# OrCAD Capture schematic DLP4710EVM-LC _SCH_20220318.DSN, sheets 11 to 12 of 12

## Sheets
11 P06: DLPC3479_GPIO,LED_SEL,TRIG: size D
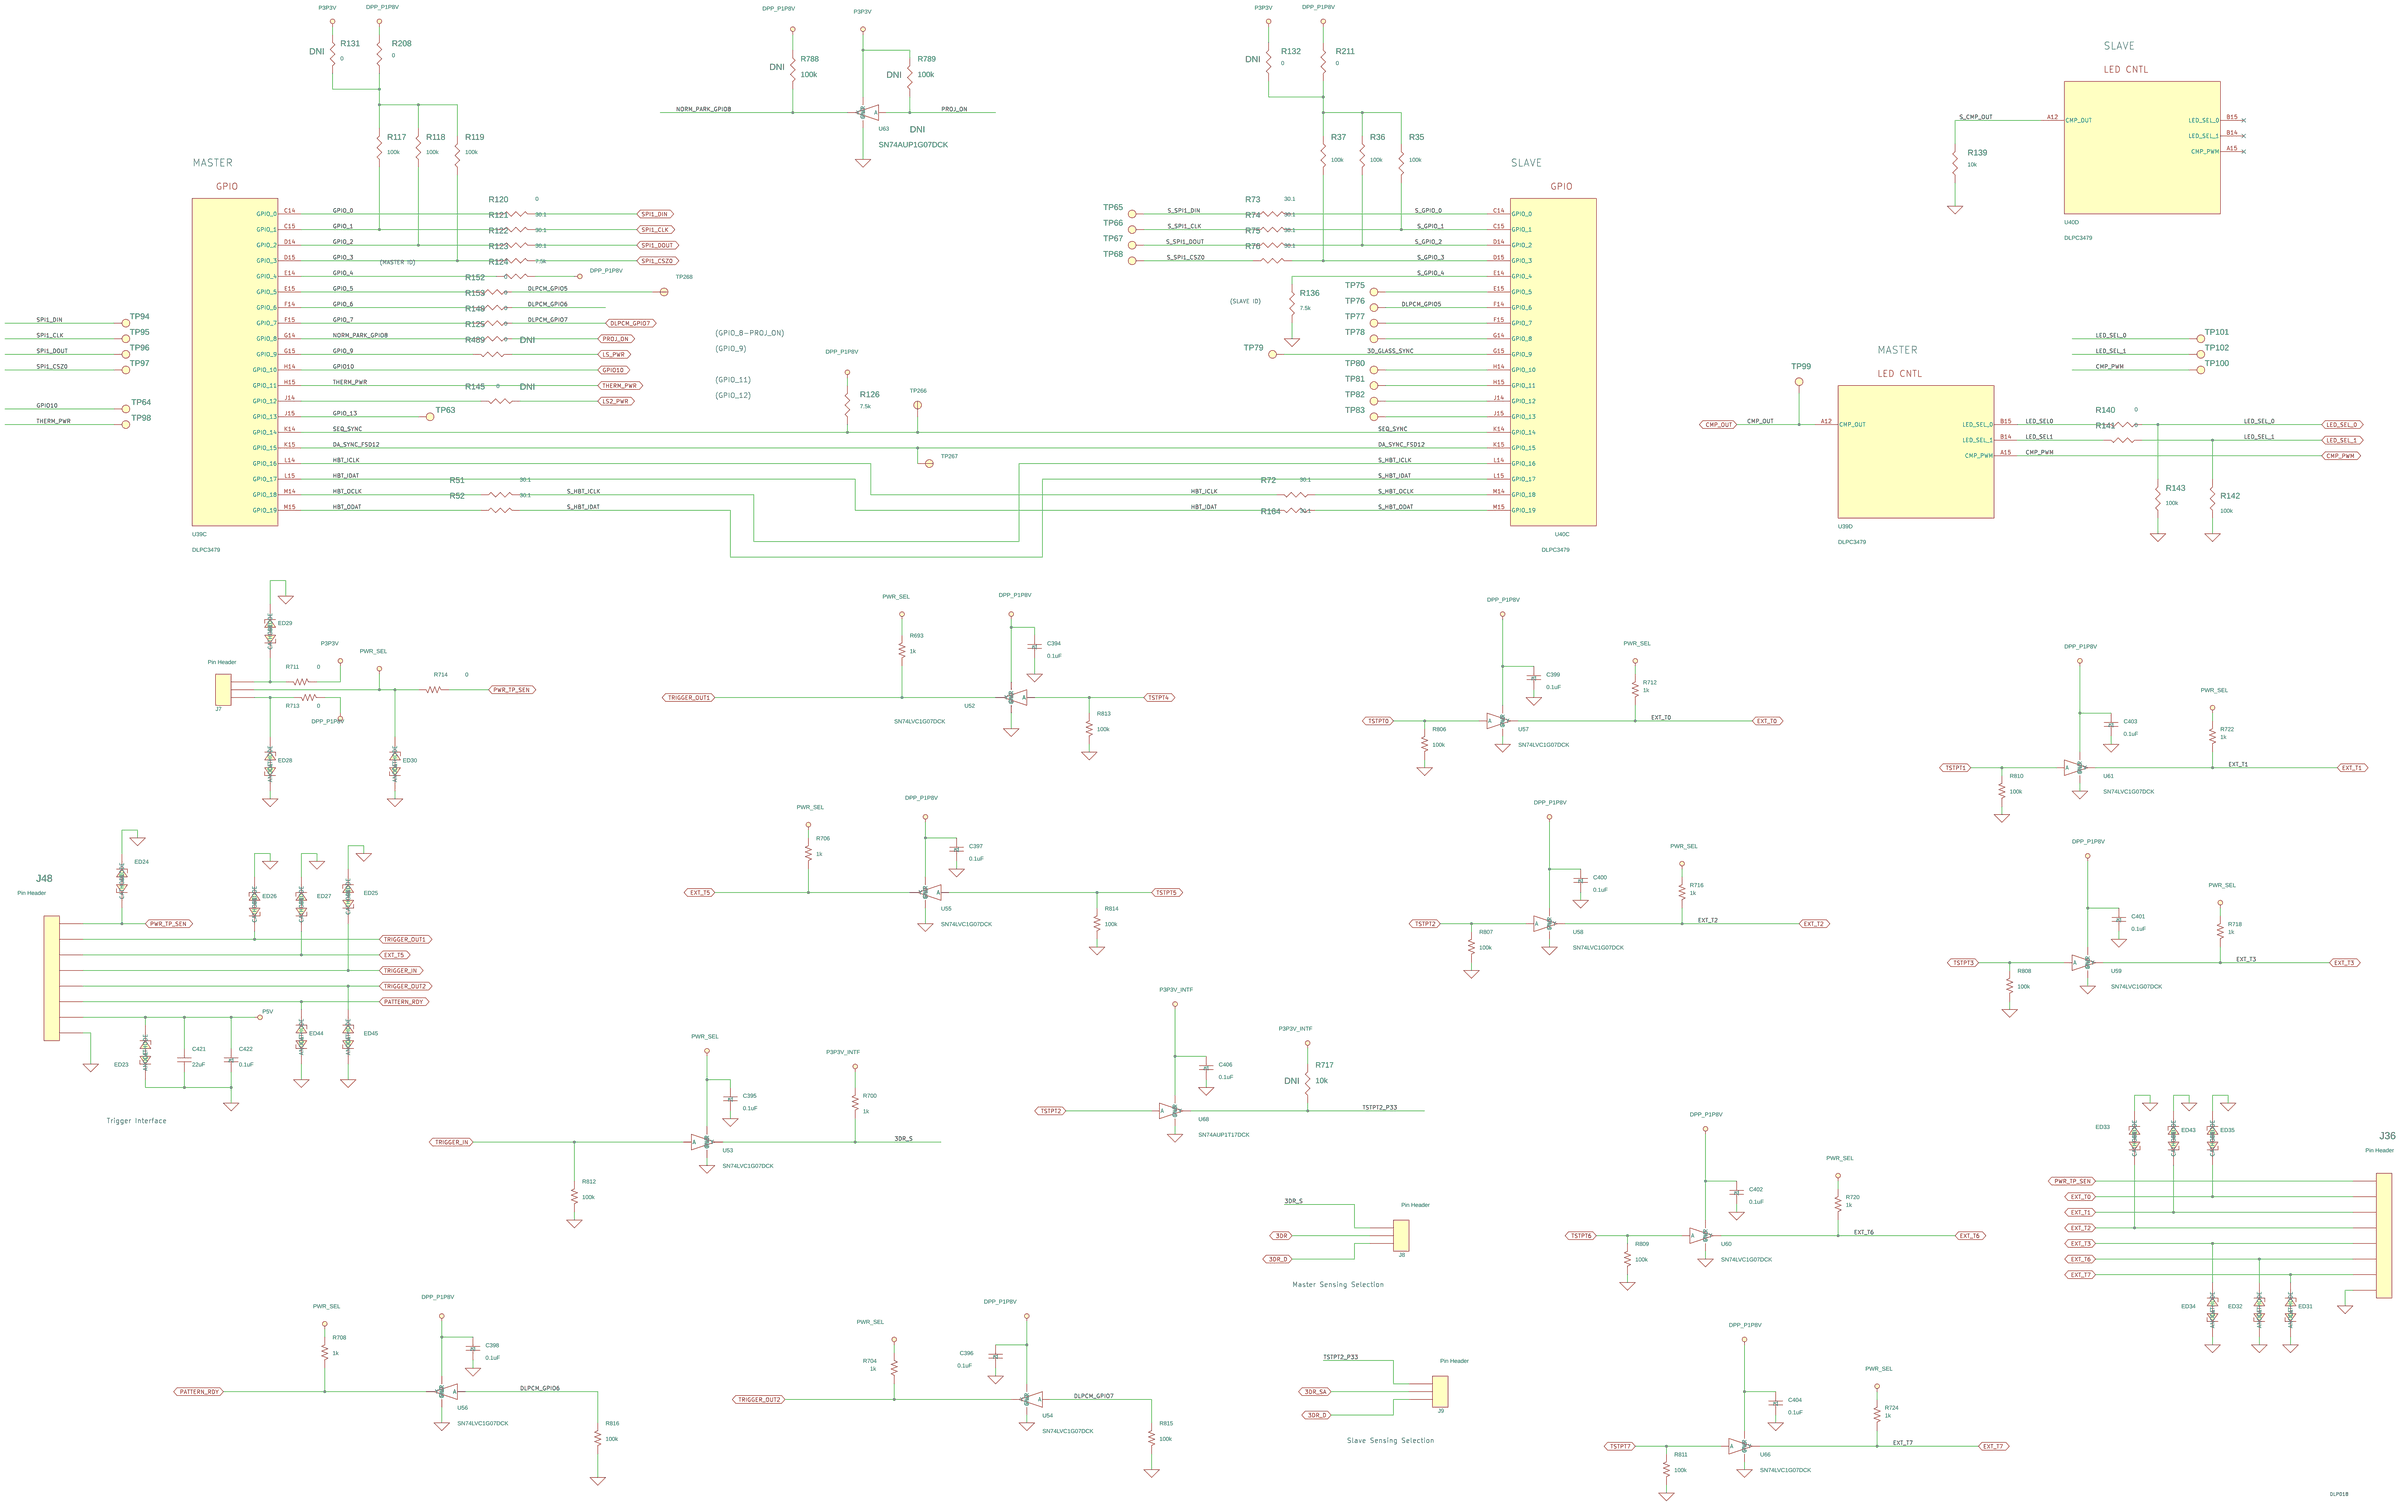
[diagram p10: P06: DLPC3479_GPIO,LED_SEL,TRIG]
12 P10: DLPA3005_PMIC & LED Driver: size D
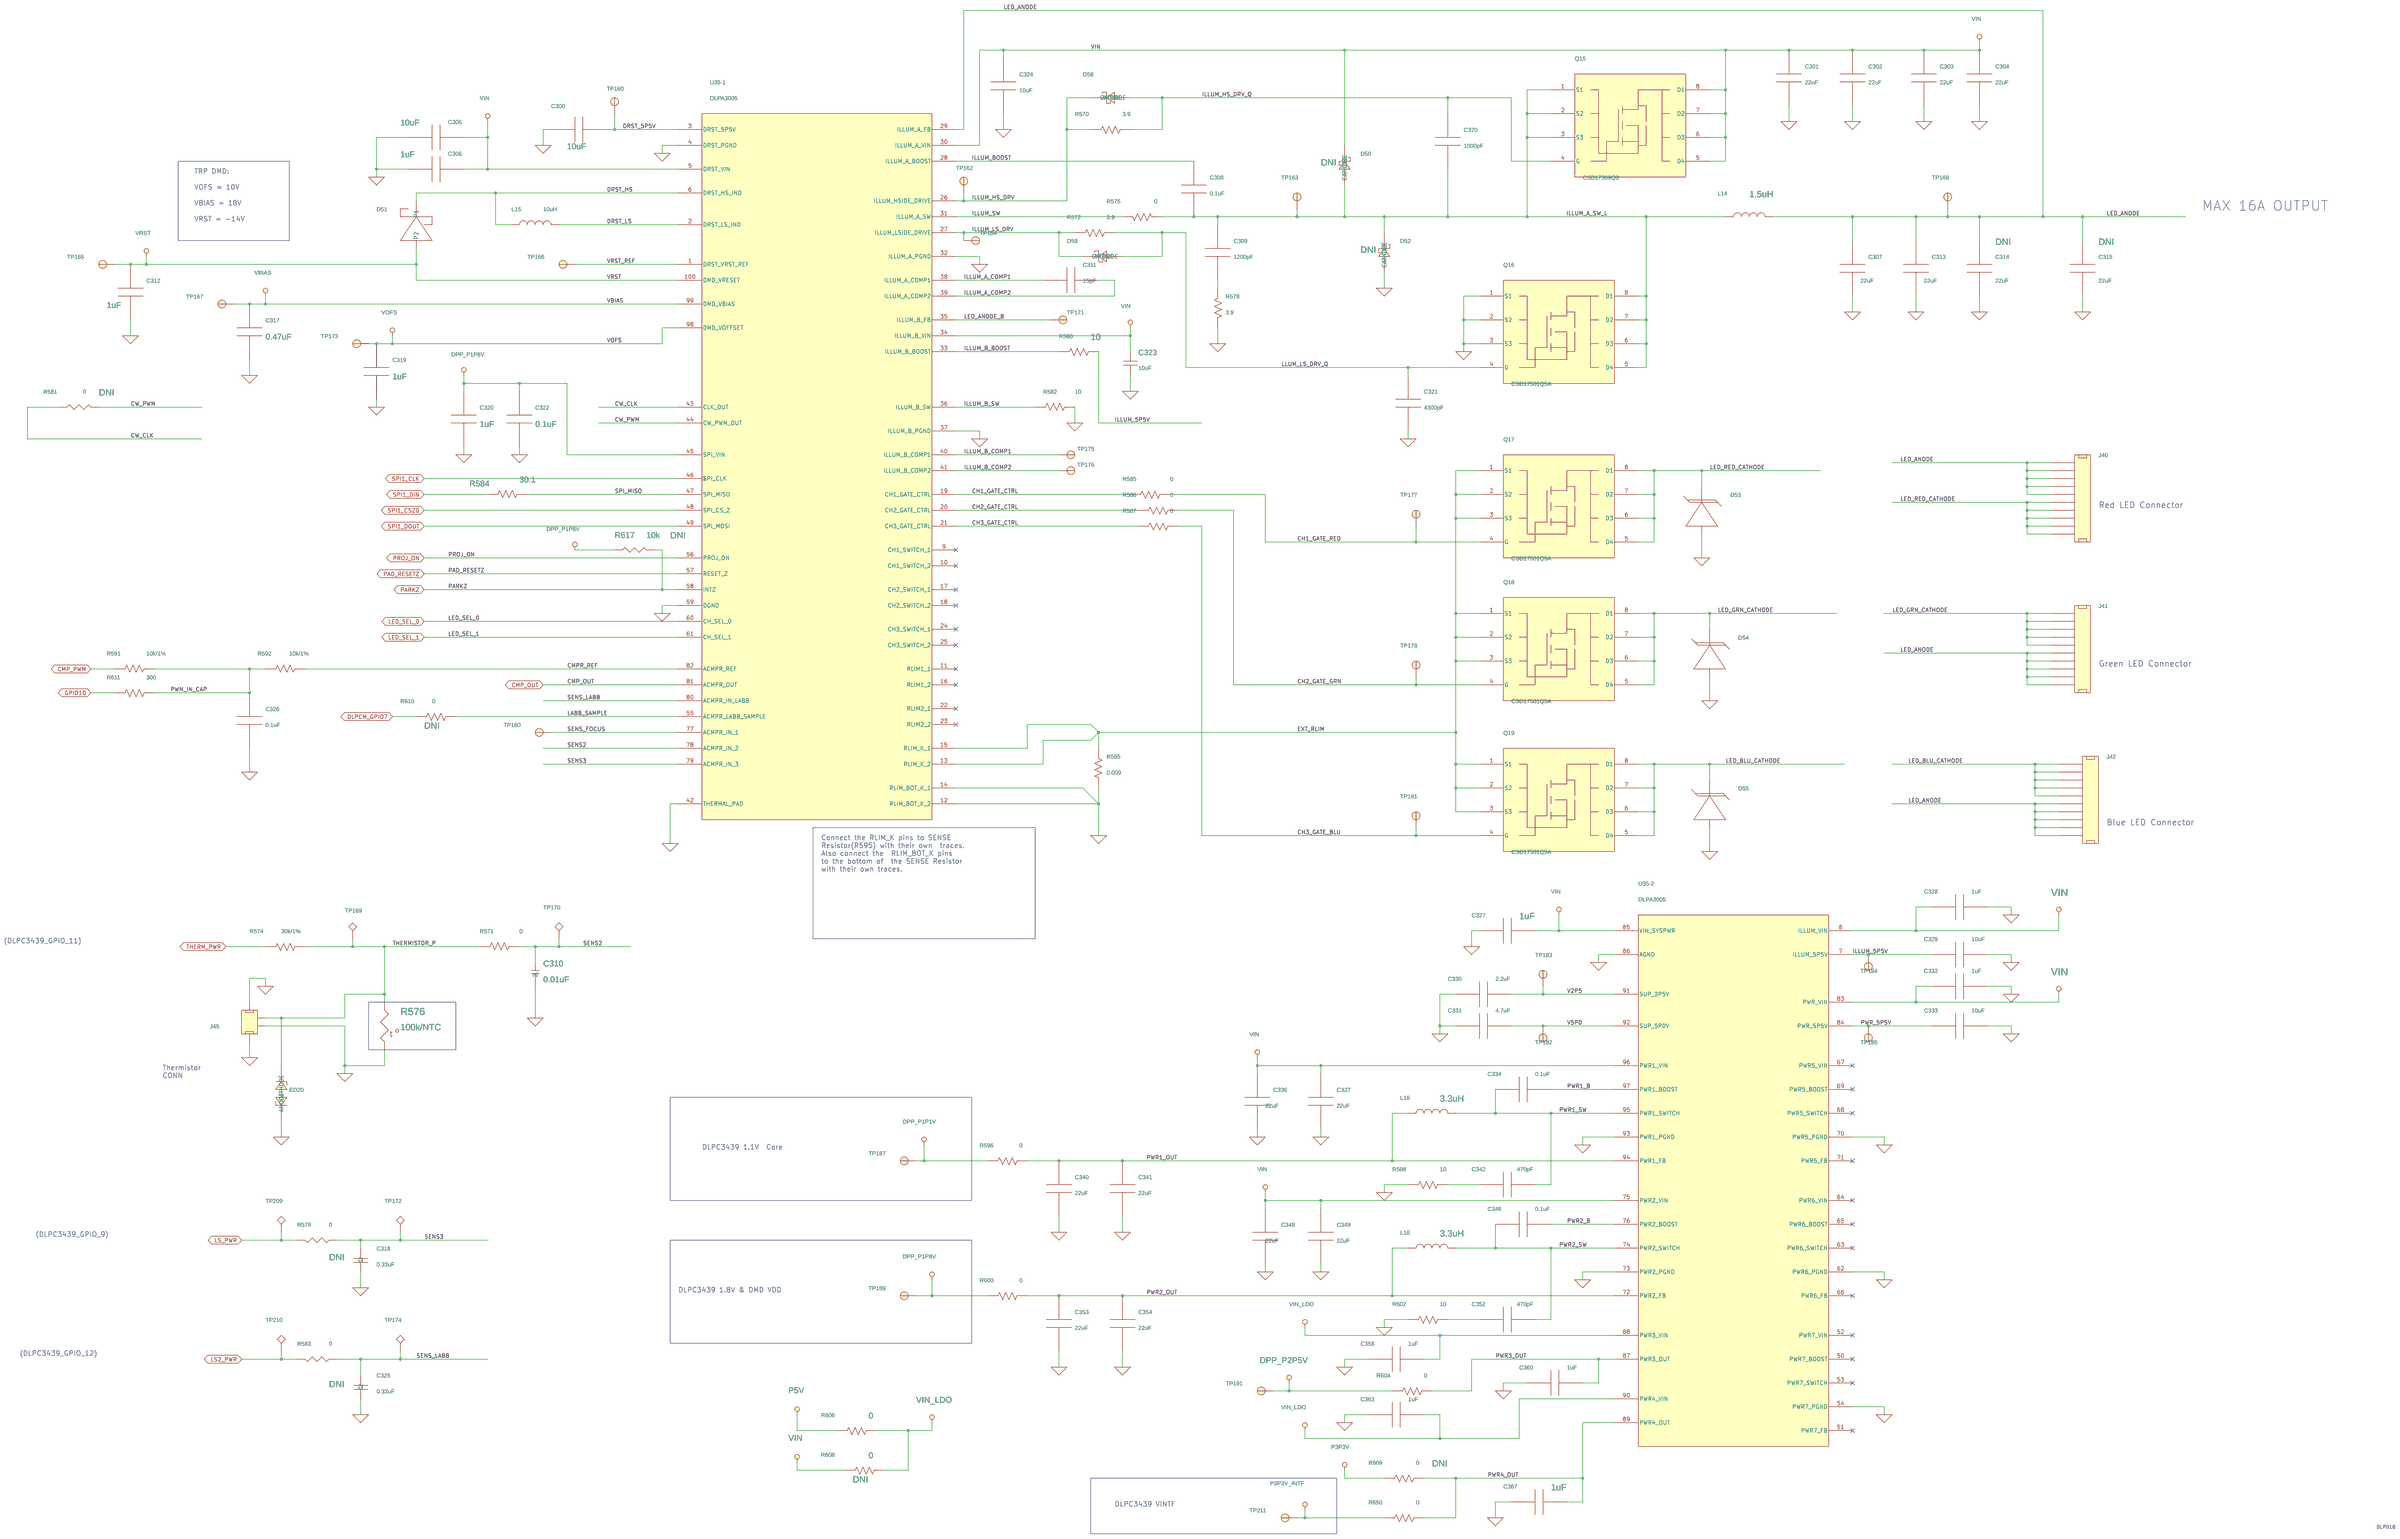
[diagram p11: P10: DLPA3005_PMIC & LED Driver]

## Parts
sheet P06: DLPC3479_GPIO,LED_SEL,TRIG
C394  0.1uF  [C0402\H0.55]
C395  0.1uF  [C0402\H0.55]
C396  0.1uF  [C0402\H0.55]
C397  0.1uF  [C0402\H0.55]
C398  0.1uF  [C0402\H0.55]
C399  0.1uF  [C0402\H0.55]
C400  0.1uF  [C0402\H0.55]
C401  0.1uF  [C0402\H0.55]
C402  0.1uF  [C0402\H0.55]
C403  0.1uF  [C0402\H0.55]
C404  0.1uF  [C0402\H0.55]
C406  0.1uF  [C0402\H0.55]
C421  22uF  [C0805\H1.35]
C422  0.1uF  [C0402\H0.55]
ED23  PESD5V0U1BL  [SOD882\2A1C\H0.5]
ED24  PESD5V0U1BL  [SOD882\2A1C\H0.5]
ED25  PESD5V0U1BL  [SOD882\2A1C\H0.5]
ED26  PESD5V0U1BL  [SOD882\2A1C\H0.5]
ED27  PESD5V0U1BL  [SOD882\2A1C\H0.5]
ED28  PESD5V0U1BL  [SOD882\2A1C\H0.5]
ED29  PESD5V0U1BL  [SOD882\2A1C\H0.5]
ED30  PESD5V0U1BL  [SOD882\2A1C\H0.5]
ED31  PESD5V0U1BL  [SOD882\2A1C\H0.5]
ED32  PESD5V0U1BL  [SOD882\2A1C\H0.5]
ED33  PESD5V0U1BL  [SOD882\2A1C\H0.5]
ED34  PESD5V0U1BL  [SOD882\2A1C\H0.5]
ED35  PESD5V0U1BL  [SOD882\2A1C\H0.5]
ED43  PESD5V0U1BL  [SOD882\2A1C\H0.5]
ED44  PESD5V0U1BL  [SOD882\2A1C\H0.5]
ED45  PESD5V0U1BL  [SOD882\2A1C\H0.5]
J7  Pin Header  [SIP3\2.54]
J8  Pin Header  [SIP3\2.54]
J9  Pin Header  [SIP3\2.54]
J36  Pin Header  [SIP8\2.54]
J48  Pin Header  [SIP8\2.54]
R35  100k  [R0402\H0.4]
R36  100k  [R0402\H0.4]
R37  100k  [R0402\H0.4]
R51  30.1  [R0402\H0.4]
R52  30.1  [R0402\H0.4]
R72  30.1  [R0402\H0.4]
R73  30.1  [R0402\H0.4]
R74  30.1  [R0402\H0.4]
R75  30.1  [R0402\H0.4]
R76  30.1  [R0402\H0.4]
R117  100k  [R0402\H0.4]
R118  100k  [R0402\H0.4]
R119  100k  [R0402\H0.4]
R120  0  [R0402\H0.4]
R121  30.1  [R0402\H0.4]
R122  30.1  [R0402\H0.4]
R123  30.1  [R0402\H0.4]
R124  7.5k  [R0402\H0.4]
R125  0  [R0402\H0.4]
R126  7.5k  [R0402\H0.4]
R131  0  [R0402\H0.4]
R132  0  [R0402\H0.4]
R136  7.5k  [R0402\H0.4]
R139  10k  [R0402\H0.4]
R140  0  [R0402\H0.4]
R141  0  [R0402\H0.4]
R142  100k  [R0402\H0.4]
R143  100k  [R0402\H0.4]
R145  0  [R0402\H0.4]
R148  0  [R0402\H0.4]
R152  0  [R0402\H0.4]
R153  0  [R0402\H0.4]
R164  30.1  [R0402\H0.4]
R208  0  [R0402\H0.4]
R211  0  [R0402\H0.4]
R489  0  [R0402\H0.4]
R693  1k  [R0402\H0.4]
R700  1k  [R0402\H0.4]
R704  1k  [R0402\H0.4]
R706  1k  [R0402\H0.4]
R708  1k  [R0402\H0.4]
R711  0  [R0402\H0.4]
R712  1k  [R0402\H0.4]
R713  0  [R0402\H0.4]
R714  0  [R0402\H0.4]
R716  1k  [R0402\H0.4]
R717  10k  [R0402\H0.4]
R718  1k  [R0402\H0.4]
R720  1k  [R0402\H0.4]
R722  1k  [R0402\H0.4]
R724  1k  [R0402\H0.4]
R788  100k  [R0402\H0.4]
R789  100k  [R0402\H0.4]
R806  100k  [R0402\H0.4]
R807  100k  [R0402\H0.4]
R808  100k  [R0402\H0.4]
R809  100k  [R0402\H0.4]
R810  100k  [R0402\H0.4]
R811  100k  [R0402\H0.4]
R812  100k  [R0402\H0.4]
R813  100k  [R0402\H0.4]
R814  100k  [R0402\H0.4]
R815  100k  [R0402\H0.4]
R816  100k  [R0402\H0.4]
TP63  Testpoint  [ICT_50]
TP64  Testpoint  [ICT_50]
TP65  Testpoint  [ICT_50]
TP66  Testpoint  [ICT_50]
TP67  Testpoint  [ICT_50]
TP68  Testpoint  [ICT_50]
TP75  Testpoint  [ICT_50]
TP76  Testpoint  [ICT_50]
TP77  Testpoint  [ICT_50]
TP78  Testpoint  [ICT_50]
TP79  Testpoint  [ICT_50]
TP80  Testpoint  [ICT_50]
TP81  Testpoint  [ICT_50]
TP82  Testpoint  [ICT_50]
TP83  Testpoint  [ICT_50]
TP94  Testpoint  [ICT_50]
TP95  Testpoint  [ICT_50]
TP96  Testpoint  [ICT_50]
TP97  Testpoint  [ICT_50]
TP98  Testpoint  [ICT_50]
TP99  Testpoint  [ICT_50]
TP100  Testpoint  [ICT_50]
TP101  Testpoint  [ICT_50]
TP102  Testpoint  [ICT_50]
TP266  Testpoint  [ICT_50]
TP267  Testpoint  [ICT_50]
TP268  Testpoint  [ICT_50]
U52  SN74LVC1G07DCK  [MCP5\0.65\H1.1]
U53  SN74LVC1G07DCK  [MCP5\0.65\H1.1]
U54  SN74LVC1G07DCK  [MCP5\0.65\H1.1]
U55  SN74LVC1G07DCK  [MCP5\0.65\H1.1]
U56  SN74LVC1G07DCK  [MCP5\0.65\H1.1]
U57  SN74LVC1G07DCK  [MCP5\0.65\H1.1]
U58  SN74LVC1G07DCK  [MCP5\0.65\H1.1]
U59  SN74LVC1G07DCK  [MCP5\0.65\H1.1]
U60  SN74LVC1G07DCK  [MCP5\0.65\H1.1]
U61  SN74LVC1G07DCK  [MCP5\0.65\H1.1]
U63  SN74AUP1G07DCK  [MCP5\0.65\H1.1]
U66  SN74LVC1G07DCK  [MCP5\0.65\H1.1]
U68  SN74AUP1T17DCK  [MCP5\0.65\H1.1]
sheet P08: DLPC3479_VDD,VSS
U39  DLPC3479  [VFBGA201\0.8\H1]  (sections A,B,C,D,E,F,G,H)
U40  DLPC3479  [VFBGA201\0.8\H1]  (sections A,B,C,D,E,F,G,H)
sheet P10: DLPA3005_PMIC & LED Driver
C300  10uF  [C0603\H0.9]
C301  22uF  [C1210\H2.8]
C302  22uF  [C1210\H2.8]
C303  22uF  [C1210\H2.8]
C304  22uF  [C1210\H2.8]
C305  10uF  [C1210\H2.8]
C306  1uF  [C0603\H0.9]
C307  22uF  [C1210\H2.8]
C308  0.1uF  [C0402\H0.55]
C309  1200pF  [C1206\H1.8]
C310  0.01uF  [C0402\H0.55]
C311  15pF  [C0402\H0.55]
C312  1uF  [C0603\H0.9]
C313  22uF  [C1210\H2.8]
C314  22uF  [C1210\H2.8]
C315  22uF  [C1210\H2.8]
C317  0.47uF  [C0603\H0.9]
C318  0.33uF  [C0402\H0.55]
C319  1uF  [C0603\H0.9]
C320  1uF  [C0402\H0.55]
C321  4300pF  [C0603\H0.9]
C322  0.1uF  [C0402\H0.55]
C323  10uF  [C0805\H1.35]
C324  10uF  [C1210\H2.8]
C325  0.33uF  [C0402\H0.55]
C326  0.1uF  [C0402\H0.55]
C327  1uF  [C0603\H0.9]
C328  1uF  [C0603\H0.9]
C329  10uF  [C0603\H0.9]
C330  2.2uF  [C0402\H0.55]
C331  4.7uF  [C0402\H0.55]
C332  1uF  [C0603\H0.9]
C333  10uF  [C0603\H0.9]
C334  0.1uF  [C0402\H0.55]
C336  22uF  [C1210\H2.8]
C337  22uF  [C1210\H2.8]
C340  22uF  [C0603\H0.9]
C341  22uF  [C0603\H0.9]
C342  470pF  [C0603\H0.9]
C346  0.1uF  [C0402\H0.55]
C348  22uF  [C1210\H2.8]
C349  22uF  [C1210\H2.8]
C352  470pF  [C0603\H0.9]
C353  22uF  [C0603\H0.9]
C354  22uF  [C0603\H0.9]
C358  1uF  [C0402\H0.55]
C360  1uF  [C0402\H0.55]
C363  1uF  [C0402\H0.55]
C367  1uF  [C0402\H0.55]
C370  1000pF  [C0603\H0.9]
D50  B240A-13-F  [DO214\SMA\H2.44]
D51  MBR0540  [SOD123\2A1C\3.75X1.6\H1.45]
D52  B240A-13-F  [DO214\SMA\H2.44]
D53  ESDA18-1K  [SOD523\2A1C\1.2X0.8\H0.7]
D54  ESDA18-1K  [SOD523\2A1C\1.2X0.8\H0.7]
D55  ESDA18-1K  [SOD523\2A1C\1.2X0.8\H0.7]
D58  B0530WS-7  [SOD323\2A1C\H1.1]
D59  B0530WS-7  [SOD323\2A1C\H1.1]
ED20  PESD5V0U1BL  [SOD882\2A1C\H0.5]
J40  78048-1043 Molex  [CON10_90\87438\1.5\H4.45]
J41  78048-1043 Molex  [CON10_90\87438\1.5\H4.45]
J42  78048-1043 Molex  [CON10_90\87438\1.5\H4.45]
J45  053261-0271 Molex  [TU1252_2S_90\1.25\H3.4]
L14  1.5uH  [IND\13.9X13.5\H5.2]
L15  10uH  [IND\MMD-04BZ\H2]
L16  3.3uH  [IND\MMD-06CZ\H3]
L18  3.3uH  [IND\MMD-06CZ\H3]
Q15  CSD17309Q3  [SON8\CSD16406Q3\0.65\H1.1]
Q16  CSD17501Q5A  [SON8\CSD17501Q5A\H1.1]
Q17  CSD17501Q5A  [SON8\CSD17501Q5A\H1.1]
Q18  CSD17501Q5A  [SON8\CSD17501Q5A\H1.1]
Q19  CSD17501Q5A  [SON8\CSD17501Q5A\H1.1]
R570  3.9  [R0603\H0.55]
R571  0  [R0402\H0.4]
R572  3.9  [R0603\H0.55]
R574  30k/1%  [R0402\H0.4]
R575  0  [R1206\H0.65]
R576  100k/NTC  [R0402\H0.4]
R578  3.9  [R1210\H0.65]
R579  0  [R0402\H0.4]
R580  10  [R0402\H0.4]
R581  0  [R0402\H0.4]
R582  10  [R0402\H0.4]
R583  0  [R0402\H0.4]
R584  30.1  [R0402\H0.4]
R585  0  [R0603\H0.55]
R586  0  [R0603\H0.55]
R587  0  [R0603\H0.55]
R591  10k/1%  [R0402\H0.4]
R592  10k/1%  [R0402\H0.4]
R595  0.009  [R2512\H0.7]
R596  0  [R1206\H0.65]
R598  10  [R0603\H0.55]
R600  0  [R1206\H0.65]
R602  10  [R0603\H0.55]
R604  0  [R0402\H0.4]
R606  0  [R1206\H0.65]
R608  0  [R1206\H0.65]
R609  0  [R0402\H0.4]
R610  0  [R0402\H0.4]
R611  300  [R0402\H0.4]
R617  10k  [R0402\H0.4]
R650  0  [R0402\H0.4]
TP160  Testpoint  [ICT_50]
TP162  Testpoint  [ICT_50]
TP163  Testpoint  [ICT_50]
TP164  Testpoint  [ICT_50]
TP165  Testpoint  [ICT_50]
TP166  Testpoint  [ICT_50]
TP167  Testpoint  [ICT_50]
TP168  Testpoint  [ICT_50]
TP169  Testpoint  [ICT_50]
TP170  Testpoint  [ICT_50]
TP171  Testpoint  [ICT_50]
TP172  Testpoint  [ICT_50]
TP173  Testpoint  [ICT_50]
TP174  Testpoint  [ICT_50]
TP175  Testpoint  [ICT_50]
TP176  Testpoint  [ICT_50]
TP177  Testpoint  [ICT_50]
TP178  Testpoint  [ICT_50]
TP180  Testpoint  [ICT_50]
TP181  Testpoint  [ICT_50]
TP182  Testpoint  [ICT_50]
TP183  Testpoint  [ICT_50]
TP184  Testpoint  [ICT_50]
TP185  Testpoint  [ICT_50]
TP187  Testpoint  [ICT_50]
TP189  Testpoint  [ICT_50]
TP191  Testpoint  [ICT_50]
TP209  Testpoint  [ICT_50]
TP210  Testpoint  [ICT_50]
TP211  Testpoint  [ICT_50]
U35  DLPA3005  [PQFP100\0.5\H1.2]  (sections -1,-2)

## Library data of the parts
C394 = CAP_0.1uF_0603_1: Ceramic CAP X7R 6.3V 0.1uF
C395 = CAP_0.1uF_0603_7: Ceramic CAP X7R 6.3V 0.1uF
C396 = CAP_0.1uF_0603_12: Ceramic CAP X7R 6.3V 0.1uF
C397 = CAP_0.1uF_0603_3: Ceramic CAP X7R 6.3V 0.1uF
C398 = CAP_0.1uF_0603: Ceramic CAP X7R 6.3V 0.1uF
C399 = CAP_0.1uF_0603_11: Ceramic CAP X7R 6.3V 0.1uF
C400 = CAP_0.1uF_0603_8: Ceramic CAP X7R 6.3V 0.1uF
C401 = CAP_0.1uF_0603_10: Ceramic CAP X7R 6.3V 0.1uF
C402 = CAP_0.1uF_0603_9: Ceramic CAP X7R 6.3V 0.1uF
C403 = CAP_0.1uF_0603_5: Ceramic CAP X7R 6.3V 0.1uF
C404 = CAP_0.1uF_0603_4: Ceramic CAP X7R 6.3V 0.1uF
C406 = CAP_0.1uF_0603_6: Ceramic CAP X7R 6.3V 0.1uF
C323 C421 = CAP_NP: ID: 114026; device: C0805
C422 = CAP_0.1uF_0603_2: Ceramic CAP X7R 6.3V 0.1uF
ED20 ED23-ED35 ED43-ED45 = DIODE_SCHOTTKY31_4
J7-J9 = CON3
J36 J48 = CON2_0
R35-R37 R51 R52 R72-R76 R117-R126 R136 R139-R143 R148 R152 R153 R164 R208 R211 = RESISTOR_SM
R131 R132 R145 R489 R617 R717 R788 R789 = RESISTOR_SM: DNI: DNI
R693 = R_v4_3
R700 = R_v4_9
R704 = R_v4_24
R706 = R_v4_20
R708 = R_v4_5
R711 = R_v4_18
R712 = R_v4_4
R713 = R_v4_2
R714 = R_v4_16
R716 = R_v4_12
R718 = R_v4_17
R720 = R_v4_14
R722 = R_v4_7
R724 = R_v4_23
R806 = R_v4_22
R807 = R_v4_10
R808 = R_v4_13
R809 = R_v4_11
R810 = R_v4_6
R811 = R_v4_19
R812 = R_v4_15
R813 = R_v4_21
R814 = R_v4
R815 = R_v4_8
R816 = R_v4_1
TP63-TP68 TP75-TP83 TP94-TP102 = T_POINT_R: Desc: TEST POINT, T/H, BLACK; Dist: Digi-Key; Dist p/n: 5001K-ND; Mfr: Keystone Electronics; Mfr p/n: 5001
TP160 TP162-TP168 TP171 TP173 TP175-TP178 TP180-TP185 TP187 TP189 TP191 TP211 TP266-TP268 = EM,TESTPOINT: Install: DNI; MFG: -- NOT A PART --; Part Specific: TP_20RD10; Type: testpoint via; Vendor: -- NOT A PART --
U52-U61 U66 U68 = TMP_0: DigiKey: 296-18256-1-ND; DigiReel: 296-18256-6-ND; Family: logic; Index PN: 1027; Install: Y; Lead Style: SMT; MFG: Texas Instruments; P/D_NUM: SN74AUP1G07DCKR; Part Number: SN74AUP1G07DCKR; Part Specific: IC BUFF/DVR LOW PWR N-INV SC705, open drain; Type: buffer
U63 = TMP_1: DNI: DNI; DigiKey: 296-18256-1-ND; DigiReel: 296-18256-6-ND; Family: logic; Index PN: 1027; Install: Y; Lead Style: SMT; MFG: Texas Instruments; P/D_NUM: SN74AUP1G07DCKR; Part Number: SN74AUP1G07DCKR; Part Specific: IC BUFF/DVR LOW PWR N-INV SC705, open drain; Type: buffer
U39 = TIDLP,DPP3438_6: DigiKey: ---; DigiReel: ---; Family: processor; Index PN: 1176; Install: Y; Lead Style: SMT; MFG: Texas Instruments; P/D_NUM: 2512737-0092; Package: Master; Part Number: 2512737-0092; Part Specific: IC, DPP3439 ASIC, DLP-PICO PROCESSOR; Type: dlp; Vendor: Texas Instruments
U40 = TIDLP,DPP3438_6: DigiKey: ---; DigiReel: ---; Family: processor; Index PN: 1176; Install: Y; Lead Style: SMT; MFG: Texas Instruments; P/D_NUM: 2512737-0092; Package: Slave; Part Number: 2512737-0092; Part Specific: IC, DPP3439 ASIC, DLP-PICO PROCESSOR; Type: dlp; Vendor: Texas Instruments
C300 = PAS,CAP,NP,large: DigiKey: 445-8920-1-ND; DigiReel: 445-8920-6-ND; Family: passive; Lead Style: SMT; MFG: TDK; Material: x5r; P/D_NUM: C1005X5R0J106M050BC; Part Number: C1005X5R0J106M050BC; TOLERANCE: 20%; Type: capacitor; VENDOR: TDK; VPC: 10V; Voltage: 6.3V
C301-C305 C324 C336 C337 C348 C349 = PAS,CAP,NP,large: DigiKey: 490-7207-1-ND; DigiReel: 490-7207-6-ND; Family: passive; Lead Style: SMT; MFG: Murata; Material: X5R; P/D_NUM: GRM219R61E106KA12D; Part Number: GRM219R61E106KA12D; Part Specific: CAP CER 10UF 25V 10% X5R 0805; TOLERANCE: 10%; Type: capacitor; VENDOR: Murata; VPC: 25V; Voltage: 25V
C306 C312 C327 C328 C332 C358 C363 = PAS,CAP,NP,large: DigiKey: 445-9081-1-ND; DigiReel: 445-9081-6-ND; Family: passive; Lead Style: SMT; MFG: TDK; Material: X5R; P/D_NUM: C1005X5R1E105M050BC; Part Number: C1005X5R1E105M050BC; Part Specific: CAP CER 1UF 25V 20% X5R 0402; TOLERANCE: 20%; Type: capacitor; VENDOR: TDK; VPC: 25V; Voltage: 25V
C307 C313 = PAS,CAP,NP,large: DigiKey: 445-8028-1-ND; DigiReel: 445-8028-6-ND; Family: passive; Lead Style: SMT; MFG: TDK; Material: X5R; P/D_NUM: C1608X5R0J226M080AC; Part Number: C1608X5R0J226M080AC; Part Specific: CAP CER 22UF 6.3V 20% X5R 0603; TOLERANCE: 20%; Type: capacitor; VENDOR: TDK; VPC: 16V; Voltage: 6.3V
C308 C311 C322 C334 C346 = PAS,CAP,NP,large: DigiKey: 445-4952-1-ND; DigiReel: 445-4952-6-ND; Family: passive; Index PN: 681; Lead Style: SMT; MFG: TDK; Material: x7r; P/D_NUM: C1005X7R1C104K050BC; Part Number: C1005X7R1C104K050BC; Part Specific: CAP CER .1UF 16V X7R 0402; TOLERANCE: 10%; Type: capacitor; VENDOR: TDK; VPC: 16V; Voltage: 16V
C309 = PAS,CAP,NP,large: DigiKey: 478-1493-1-ND; DigiReel: 478-1493-6-ND; Family: passive; Install: Y; Lead Style: SMT; MFG: AVX; Material: npo; P/D_NUM: 12065A122JAT2A; Part Number: 12065A122JAT2A; Part Specific: CAP CER 1200PF 50V 5% NP0 1206; TOLERANCE: 5%; Type: capacitor; VENDOR: AVX; VPC: 50V; Voltage: 50V
C310 = C_1
C314 C315 = PAS,CAP,NP,large: DNI: DNI; DigiKey: 445-8028-1-ND; DigiReel: 445-8028-6-ND; Family: passive; Lead Style: SMT; MFG: TDK; Material: X5R; P/D_NUM: C1608X5R0J226M080AC; Part Number: C1608X5R0J226M080AC; Part Specific: CAP CER 22UF 6.3V 20% X5R 0603; TOLERANCE: 20%; Type: capacitor; VENDOR: TDK; VPC: 16V; Voltage: 6.3V
C317 C319 = PAS,CAP,NP,large: DigiKey: 445-8020-1-ND; DigiReel: 445-8020-6-ND; Family: passive; Lead Style: SMT; MFG: TDK; Material: X5R; P/D_NUM: C1005X5R1E474K050BB; Part Number: C1005X5R1E474K050BB; Part Specific: CAP CER 0.47UF 25V 10% X5R 0402; Type: capacitor; VENDOR: TDK; VPC: 25V; Voltage: 25V
C318 = CAP_0.1uF_0603_1: Ceramic CAP X7R 6.3V 0.1uF; DNI: DNI
C320 C360 C367 = PAS,CAP,NP,large: DigiKey: 445-4991-1-ND; DigiReel: 445-4991-6-ND; Family: passive; Index PN: 916; Lead Style: SMT; MFG: TDK; Material: x5r; P/D_NUM: C1005X5R1A105M; Part Number: C1005X5R1A105M; TOLERANCE: 20%; Type: capacitor; VENDOR: TDK; VPC: 10V
C321 C370 = PAS,CAP,NP,large: DigiKey: 445-1291-1-ND; DigiReel: 445-1291-6-ND; Family: passive; Install: Y; Lead Style: SMT; MFG: TDK; Material: npo; P/D_NUM: C1608C0G1H681J080AA; Part Number: C1608C0G1H681J080AA; Part Specific: CAP CER 680PF 50V 5% NP0 0603; TOLERANCE: 5%; Type: capacitor; VENDOR: TDK; VPC: 50V; Voltage: 50V
C325 = CAP_0.1uF_0603: Ceramic CAP X7R 6.3V 0.1uF; DNI: DNI
C326 = PAS,CAP,NP,large: DigiKey: 445-4952-1-ND; DigiReel: 445-4952-6-ND; Family: passive; Index PN: 681; Lead Style: SMT; MFG: TDK; Material: x7r; P/D_NUM: C1005X7R1C104K050BC; Part Number: C1005X7R1C104K050BC; Part Specific: CAP CER .1UF 16V X7R 0402; TOLERANCE: 10%; Type: capacitor; VENDOR: TDK; VPC: 16V; Voltage: 25V
C329 C333 = PAS,CAP,NP,large: DigiKey: 445-4991-1-ND; DigiReel: 445-4991-6-ND; Family: passive; Index PN: 916; Lead Style: SMT; MFG: TDK; Material: x5r; P/D_NUM: C1005X5R1A105M; Part Number: C1005X5R1A105M; Part Specific: CAP CER 1.0UF 10V X5R 0402; TOLERANCE: 20%; Type: capacitor; VENDOR: TDK; VPC: 10V
C330 = PAS,CAP,NP,large: DigiKey: 445-4999-1-ND; DigiReel: 445-4999-6-ND; Family: passive; Index PN: 915; Lead Style: SMT; MFG: TDK; Material: X5R; P/D_NUM: C1005X5R0J225M; Part Number: C1005X5R0J225M; Part Specific: CAP CER 2.2UF 6.3V 20% X5R 0402; TOLERANCE: 20%; Type: capacitor; VENDOR: TDK; VPC: 6.3V; Voltage: 6.3V
C331 = PAS,CAP,NP,large: DigiKey: 445-7395-1-ND; DigiReel: 445-7395-6-ND; Family: passive; Lead Style: SMT; MFG: TDK; Material: X5R; P/D_NUM: C1005X5R0J475M050BC; Part Number: C1005X5R0J475M050BC; Part Specific: CAP CER 4.7UF 6.3V 20% X5R 0402; TOLERANCE: 20%; Type: capacitor; VENDOR: TDK; VPC: 6.3V; Voltage: 6.3V
C340 C341 C353 C354 = PAS,CAP,NP,large: DigiKey: 445-8028-1-ND; DigiReel: 445-8028-6-ND; Family: passive; Lead Style: SMT; MFG: TDK; Material: X5R; P/D_NUM: C1608X5R0J226M080AC; Part Number: C1608X5R0J226M080AC; Part Specific: CAP CER 22UF 6.3V 20% X5R 0603; TOLERANCE: 20%; Type: capacitor; VENDOR: TDK; VPC: 6.3V; Voltage: 6.3V
C342 C352 = PAS,CAP,NP,large: DigiKey: 445-1289-1-ND; DigiReel: 445-1289-6-ND; Family: passive; Install: Y; Lead Style: SMT; MFG: TDK; Material: npo; P/D_NUM: C1608C0G1H471J080AA; Part Number: C1608C0G1H471J080AA; Part Specific: CAP CER 470PF 50V 5% NP0 0603; TOLERANCE: 5%; Type: capacitor; VENDOR: TDK; VPC: 50V; Voltage: 50V
D50 D52 = DIODE_SCHOTTKY31_2: DNI: DNI
D51 = PAS,DIODE,SCHOTTKY,large_0: DigiKey: MBR0540CT-ND; DigiReel: MBR0540DKR-ND; Family: passive; Lead Style: SMT; MFG: Fairchild Semiconductor; Part Specific: SCHOTTKY RECT 40V 0.5A SOD123; Type: diode,schottky; VENDOR: Fairchild Semiconductor; VPC: 0.5A; Voltage: 40V
D53 = PAS,DIODE,TVS,large_4: DigiKey: 497-10767-1-ND; DigiReel: 497-10767-6-ND; Lead Style: SMT; MFG: STMicroelectronics; Part Specific: DIODE TVS 18V 450W SOD523; Type: Diode,TVS; VENDOR: STMicroelectronics; VPC: 18V; Voltage: 18V
D54 = PAS,DIODE,TVS,large_5: DigiKey: 497-10767-1-ND; DigiReel: 497-10767-6-ND; Lead Style: SMT; MFG: STMicroelectronics; Part Specific: DIODE TVS 18V 450W SOD523; Type: Diode,TVS; VENDOR: STMicroelectronics; VPC: 18V; Voltage: 18V
D55 = PAS,DIODE,TVS,large_6: DigiKey: 497-10767-1-ND; DigiReel: 497-10767-6-ND; Lead Style: SMT; MFG: STMicroelectronics; Part Specific: DIODE TVS 18V 450W SOD523; Type: Diode,TVS; VENDOR: STMicroelectronics; VPC: 18V; Voltage: 18V
D58 D59 = DIODE_SCHOTTKY31_3
J40-J42 = CONN_SOCKET_10
J45 = CONN_SOCKET_2_1
L14 = PAS,INDUCTOR,_large: DigiKey: ---; DigiReel: ---; Family: passive; Lead Style: SMT; MFG: Coilcraft; P/D_NUM: XAL7030-272MEB; Part Number: MMD-12EZ-1R5M-V1; Part Specific: Inductor 2.7uH 9.2A 20% SMD; Type: inductor; VENDOR: Coilcraft; VPC: 9.2A
L15 = PAS,INDUCTOR,_large: Family: passive; Lead Style: SMT; MFG: Coilcraft; P/D_NUM: LPS4018-103MLB; Part Number: 03.10003G352--10uH 1.6A-MMD-04BZ-100M-S1; Part Specific: INDUCTOR 10UH 20% 0.9A SMD; Type: inductor; VENDOR: Coilcraft; VPC: 0.9A
L16 L18 = PAS,INDUCTOR,_large: DigiKey: 541-1221-1-ND; DigiReel: 541-1221-6-ND; Family: passive; Lead Style: SMT; MFG: Vishay Dale; P/D_NUM: IHLP2020BZER3R3M11; Part Number: MMD-06CZ-3R3M-V1; Part Specific: INDUCTOR POWER 3.3UH 4.1A SMD; Type: inductor; VENDOR: Vishay Dale; VPC: 4.1A
Q15-Q19 = ANA,FET,CSD16342Q5A: DigiKey: 296-30314-1-ND; DigiReel: 296-30314-6-ND; Family: analog; Install: Y; Lead Style: SMT; MFG: Texas Instruments; P/D_NUM: CSD16342Q5A; Part Number: CSD16342Q5A; Part Specific: MOSFET N-CH 25V 100A 8SON; Pin Cnt: 8; Type: MOSFET; VENDOR: Texas Instruments; VPC: 100A; Voltage: 25V
R570 R572 R580 R582 R585-R587 R604 R611 R650 = PAS,R,large: DigiKey: P0.0JCT-ND; DigiReel: P0.0JDKR-ND; Family: passive; Index PN: 687; Install: DNI; Lead Style: SMT; MFG: Panasonic; Material: chip; P/D_NUM: ERJ-2GE0R00X; Part Number: ERJ-2GE0R00X; Part Specific: RES 0.0 OHM 1/16W 0402 SMD; Power: 1/16W; Type: resistor; VPC: 1/16W; Vendor: Panasonic
R571 = PAS,R,large: DigiKey: P0.0JCT-ND; DigiReel: P0.0JDKR-ND; Family: passive; Index PN: 687; Lead Style: SMT; MFG: Panasonic; Material: chip; P/D_NUM: ERJ-2GE0R00X; Part Number: ERJ-2GE0R00X; Part Specific: RES 0.0 OHM 1/16W 0402 SMD; Power: 1/16W; Type: resistor; VPC: 1/16W; Vendor: Panasonic
R574 = PAS,R,large: DigiKey: P30.0KLCT-ND; DigiReel: P30.0KLDKR-ND; Family: passive; Index PN: 909; Lead Style: SMT; MFG: Panasonic; Material: chip; P/D_NUM: ERJ-2RKF3002X; Part Number: ERJ-2RKF3002X; Part Specific: RES 30.0K OHM 1/10W 1% 0402 SMD; Power: 1/16W; Tolerance: 1%; Type: resistor; VPC: 1/16W; Vendor: Panasonic
R575 R596 R600 R606 = PAS,R,large: DigiKey: 541-1890-1-ND; DigiReel: 541-1890-6-ND; Family: passive; Install: DNI; Lead Style: SMT; MFG: Vishay; Material: chip; P/D_NUM: RCG12060000Z0EA; Part Number: RCG12060000Z0EA; Part Specific: RES 0.0 OHM 3.5A JUMP 1206 SMD; Power: 1/4W; Type: resistor; VENDOR: Panasonic; VPC: 1/16W
R576 = PAS,THERMISTOR,large: DigiKey: 490-4803-1-ND; DigiReel: 490-4803-6-ND; Family: passive; Index PN: 910; Lead Style: SMT; MFG: Murata; P/D_NUM: NCP15WF104F03RC; Part Number: NCP15WF104F03RC; Part Specific: THERMISTOR 100K OHM NTC 0402 SMD; TOLERANCE: 1%; Type: thermistor; VENDOR: Murata
R578 = PAS,R,large: DigiKey: RHM3.9AXCT-ND; DigiReel: RHM3.9AXDKR-ND; Family: passive; Install: Y; Lead Style: SMT; MFG: Rohm; Material: chip; P/D_NUM: ESR25JZPJ3R9; Part Number: ESR25JZPJ3R9; Part Specific: RES 3.9 OHM 1/2W 5% 1210 SMD; Power: 1/2W; TOLERANCE: 5%; Type: resistor; VPC: 1/2W; Vendor: Rohm
R579 = R: Part Description: RESISTOR 10K OHMS 1/10W 5% 0603; Part Type: 5%\0603; Sierra Part#: 1200100-103; Tolerance: 5%
R581 = R_1: DNI: DNI
R583 = R_2: Part Description: RESISTOR 10K OHMS 1/10W 5% 0603; Part Type: 5%\0603; Sierra Part#: 1200100-103; Tolerance: 5%
R584 R591 R592 = PAS,R,large: DigiKey: P10.0KLCT-ND; DigiReel: P10.0KLDKR-ND; Family: passive; Index PN: 680; Lead Style: SMT; MFG: Panasonic; Material: chip; P/D_NUM: ERJ-2RKF1002X; Part Number: ERJ-2RKF1002X; Part Specific: RES 10K OHM 1/10W 1% 0402 SMD; Power: 1/16W; Tolerance: 1%; Type: resistor; VPC: 1/16W; Vendor: Panasonic
R595 = PAS,R,large: DigiKey: 989-1041-1-ND; DigiReel: 989-1041-6-ND; Family: passive; Lead Style: SMT; MFG: TT Electronics; Material: chip; P/D_NUM: LRC-LRF2010LF-01-R025F; Part Number: LRC-LRF2010LF-01-R025F; Part Specific: RES .025 OHM 1W 1% 2010 SMD; Tolerance: 1%; Type: resistor; VPC: 3W; Vendor: TT Electronics
R598 R602 = PAS,R,large: DigiKey: RHM10.0ADCT-ND; DigiReel: RHM10.0ADDKR-ND; Family: passive; Install: Y; Lead Style: SMT; MFG: Rohm; Material: chip; P/D_NUM: ESR03EZPF10R0; Part Number: ESR03EZPF10R0; Part Specific: RES 10 OHM 1/4W 1% 0603 SMD; Power: 1/4W; TOLERANCE: 1%; Type: resistor; VPC: 1/4W; Vendor: Panasonic
R608 = PAS,R,large: DNI: DNI; Family: passive; Install: DNI; Lead Style: SMT; MFG: Vishay; Material: chip; P/D_NUM: RCG12060000Z0EA; Part Number: RCG12060000Z0EA; Part Specific: RES 0.0 OHM 3.5A JUMP 1206 SMD; Power: 1/4W; Type: resistor; VENDOR: Panasonic; VPC: 1/16W
R609 R610 = PAS,R,large: DNI: DNI; DigiKey: P0.0JCT-ND; DigiReel: P0.0JDKR-ND; Family: passive; Index PN: 687; Install: DNI; Lead Style: SMT; MFG: Panasonic; Material: chip; P/D_NUM: ERJ-2GE0R00X; Part Number: ERJ-2GE0R00X; Part Specific: RES 0.0 OHM 1/16W 0402 SMD; Power: 1/16W; Type: resistor; VPC: 1/16W; Vendor: Panasonic
TP169 TP170 TP172 TP174 TP209 TP210 = BF,HOLE,PLATED,TESTPIN: DigiKey: ---; DigiReel: ---; Family: board feature; Index PN: 377; Install: DNI; Lead Style: TH; MFG: -- NOT A PART --; Part Specific: TP; Type: hole,plated; Vendor: -- NOT A PART --
U35 = TIDLP,PAD3000_V2_2: MFG: Texas Instruments; Part Number: PAD3005; Part Specific: IC PMIC LED DRIVER; Pin Cnt: 100; Vendor: Texas Instruments; Color: Default; Install: Y; Location X-Coordinate: 0; Location Y-Coordinate: 0; Power Pins Visible: False; Primitive: DEFAULT; SPLIT_INST: TRUE; SWAP_INFO: (S1+S2)

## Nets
DGND: C300.1(P) C301.2(N) C302.2(N) C303.2(N) C304.2(N) C305.2(N) C306.2(N) C307.2(N) C310.2 C312.2(N) C313.2(N) C314.2(N) C315.2(N) C317.2(N) C318.1 C319.2(N) C320.2(N) C321.2(N) C322.2(N) C323.2 C324.2(N) C325.1 C326.2(N) C327.2(N) C328.2(N) C329.2(N) C330.1(P) C331.1(P) C332.2(N) C333.2(N) C336.2(N) C337.2(N) C340.2(N) C341.2(N) C348.2(N) C349.2(N) C353.2(N) C354.2(N) C358.2(N) C360.2(N) C363.2(N) C367.2(N) C394.2 C395.2 C396.2 C397.2 C398.2 C399.2 C400.2 C401.2 C402.2 C403.2 C404.2 C406.2 C421.2 C422.2 D52.A(ANODE) D53.A D54.A D55.A ED20.A(ANODE) ED23.A(ANODE) ED24.A(ANODE) ED25.A(ANODE) ED26.A(ANODE) ED27.A(ANODE) ED28.A(ANODE) ED29.A(ANODE) ED30.A(ANODE) ED31.A(ANODE) ED32.A(ANODE) ED33.A(ANODE) ED34.A(ANODE) ED35.A(ANODE) ED43.A(ANODE) ED44.A(ANODE) ED45.A(ANODE) J36.1 J45.2 J45.3 J45.4 J48.1 Q16.1(S1) Q16.2(S2) Q16.3(S3) R136.2 R139.2 R142.1 R143.1 R576.2 R578.1(N1) R582.2(N2) R595.1(N1) R598.2(N2) R602.2(N2) R806.1 R807.1 R808.1 R809.1 R810.1 R811.1 R812.1 R813.1 R814.1 R815.1 R816.1 U35.4(DRST_PGND) U35.12(RLIM_BOT_K_2) U35.14(RLIM_BOT_K_1) U35.32(ILLUM_A_PGND) U35.37(ILLUM_B_PGND) U35.42(THERMAL_PAD) U35.54(PWR7_PGND) U35.59(DGND) U35.62(PWR6_PGND) U35.70(PWR5_PGND) U35.73(PWR2_PGND) U35.86(AGND) U35.93(PWR1_PGND) U52.3(GND) U53.3(GND) U54.3(GND) U55.3(GND) U56.3(GND) U57.3(GND) U58.3(GND) U59.3(GND) U60.3(GND) U61.3(GND) U63.3(GND) U66.3(GND) U68.3(GND) ; also on sheet 1 2 5 6 7 8 9 10
P5V: C421.1 C422.1 ED23.C(CATHODE) J48.2 R606.2(N2) ; also on sheet 2 6 8 10
V2P5: C330.2(N) TP183.1(P1) U35.91(SUP_2P5V)
V5P0: C331.2(N) TP182.1(P1) U35.92(SUP_5P0V)
VIN: C301.1(P) C302.1(P) C303.1(P) C304.1(P) C305.1(P) C306.1(P) C323.1 C324.1(P) C327.1(P) C328.1(P) C332.1(P) C336.1(P) C337.1(P) C348.1(P) C349.1(P) D50.C(CATHODE) Q15.5(D4) Q15.6(D3) Q15.7(D2) Q15.8(D1) R608.2(N2) U35.5(DRST_VIN) U35.8(ILLUM_VIN) U35.30(ILLUM_A_VIN) U35.34(ILLUM_B_VIN) U35.75(PWR2_VIN) U35.83(PWR_VIN) U35.85(VIN_SYSPWR) U35.96(PWR1_VIN) ; also on sheet 8
VIN_LDO: C358.1(P) C363.1(P) R606.1(N1) R608.1(N1) U35.88(PWR3_VIN) U35.90(PWR4_VIN)
3D_GLASS_SYNC: TP79.1(TP) U40.G15(GPIO_9)
3DR: J8.2 ; also on sheet 9
3DR_D: J8.1 J9.1 ; also on sheet 6
3DR_S: J8.3 R700.1 U53.4(Y)
3DR_SA: J9.2 ; also on sheet 9
CH1_GATE_CTRL: R585.2(N2) U35.19(CH1_GATE_CTRL)
CH1_GATE_RED: Q17.4(G) R585.1(N1) TP177.1(P1)
CH2_GATE_CTRL: R586.2(N2) U35.20(CH2_GATE_CTRL)
CH2_GATE_GRN: Q18.4(G) R586.1(N1) TP178.1(P1)
CH3_GATE_BLU: Q19.4(G) R587.1(N1) TP181.1(P1)
CH3_GATE_CTRL: R587.2(N2) U35.21(CH3_GATE_CTRL)
CMP_OUT: TP99.1(TP) U35.81(ACMPR_OUT) U39.A12(CMP_OUT)
CMP_PWM: R591.1(N1) TP100.1(TP) U39.A15(CMP_PWM)
CMPR_REF: R592.2(N2) U35.82(ACMPR_REF)
CW_CLK: R581.1 U35.43(CLK_OUT)
CW_PWM: R581.2 U35.44(CW_PWM_OUT)
DA_SYNC_FSD12: TP267.1(P1) U39.K15(GPIO_15) U40.K15(GPIO_15)
DLPCM_GPIO5: R152.1 TP76.1(TP) TP268.1(P1) U40.F14(GPIO_6)
DLPCM_GPIO6: R153.1 R816.2 U56.2(A)
DLPCM_GPIO7: R148.1 R610.2(N2) R815.2 U54.2(A)
DPP_P1P1V: R596.2(N2) TP187.1(P1) ; also on sheet 1
DPP_P1P8V: C320.1(P) C322.1(P) C394.1 C396.1 C397.1 C398.1 C399.1 C400.1 C401.1 C402.1 C403.1 C404.1 R124.2 R126.2 R208.2 R211.2 R600.2(N2) R617.1 R713.1 R788.1 TP189.1(P1) U35.45(SPI_VIN) U52.5(PWR) U54.5(PWR) U55.5(PWR) U56.5(PWR) U57.5(PWR) U58.5(PWR) U59.5(PWR) U60.5(PWR) U61.5(PWR) U66.5(PWR) ; also on sheet 1 2 5 6 9 10
DPP_P2P5V: R604.2(N2) TP191.1(P1)
DRST_5P5V: C300.2(N) TP160.1(P1) U35.3(DRST_5P5V)
DRST_HS: D51.C(P1) L15.1 U35.6(DRST_HS_IND)
DRST_LS: L15.2 U35.2(DRST_LS_IND)
EXT_RLIM: Q17.1(S1) Q17.2(S2) Q17.3(S3) Q18.1(S1) Q18.2(S2) Q18.3(S3) Q19.1(S1) Q19.2(S2) Q19.3(S3) R595.2(N2) U35.13(RLIM_K_2) U35.15(RLIM_K_1)
EXT_T0: ED35.C(CATHODE) J36.7 R712.1 U57.4(Y)
EXT_T1: ED43.C(CATHODE) J36.6 R722.1 U61.4(Y)
EXT_T2: ED33.C(CATHODE) J36.5 R716.1 U58.4(Y)
EXT_T3: ED34.C(CATHODE) J36.4 R718.1 U59.4(Y)
EXT_T5: ED27.C(CATHODE) J48.6 R706.1 U55.4(Y)
EXT_T6: ED32.C(CATHODE) J36.3 R720.1 U60.4(Y)
EXT_T7: ED31.C(CATHODE) J36.2 R724.1 U66.4(Y)
GPIO10: R611.2(N2) TP64.1(TP) U39.H14(GPIO_10)
GPIO_0: R120.1 U39.C14(GPIO_0)
GPIO_1: R117.1 R121.1 U39.C15(GPIO_1)
GPIO_2: R118.1 R122.1 U39.D14(GPIO_2)
GPIO_3: R119.1 R123.1 U39.D15(GPIO_3)
GPIO_4: R124.1 U39.E14(GPIO_4)
GPIO_5: R152.2 U39.E15(GPIO_5)
GPIO_6: R153.2 U39.F14(GPIO_6)
GPIO_7: R148.2 U39.F15(GPIO_7)
GPIO_9: R489.2 U39.G15(GPIO_9)
GPIO_13: TP63.1(TP) U39.J15(GPIO_13)
HBT_ICLK: R72.2 U39.L14(GPIO_16)
HBT_IDAT: R164.2 U39.L15(GPIO_17)
HBT_OCLK: R51.1 U39.M14(GPIO_18)
HBT_ODAT: R52.1 U39.M15(GPIO_19)
ILLUM_5P5V: C329.1(P) R580.1(N1) TP184.1(P1) U35.7(ILLUM_5P5V)
ILLUM_A_COMP1: C311.2(N) U35.38(ILLUM_A_COMP1)
ILLUM_A_COMP2: C311.1(P) U35.39(ILLUM_A_COMP2)
ILLUM_A_SW_L: C308.2(N) C309.1(P) C370.2(N) D50.A(ANODE) D52.C(CATHODE) L14.2 Q15.1(S1) Q15.2(S2) Q15.3(S3) Q16.5(D4) Q16.6(D3) Q16.7(D2) Q16.8(D1) R575.2(N2) TP163.1(P1)
ILLUM_B_BOOST: R580.2(N2) U35.33(ILLUM_B_BOOST)
ILLUM_B_COMP1: TP175.1(P1) U35.40(ILLUM_B_COMP1)
ILLUM_B_COMP2: TP176.1(P1) U35.41(ILLUM_B_COMP2)
ILLUM_B_SW: R582.1(N1) U35.36(ILLUM_B_SW)
ILLUM_BOOST: C308.1(P) U35.28(ILLUM_A_BOOST)
ILLUM_HS_DRV: D58.C(CATHODE) R570.2(N2) TP162.1(P1) U35.26(ILLUM_HSIDE_DRIVE)
ILLUM_HS_DRV_Q: C370.1(P) D58.A(ANODE) Q15.4(G) R570.1(N1)
ILLUM_LS_DRV: D59.C(CATHODE) R572.2(N2) TP164.1(P1) U35.27(ILLUM_LSIDE_DRIVE)
ILLUM_SW: R575.1(N1) U35.31(ILLUM_A_SW)
LABB_SAMPLE: R610.1(N1) U35.55(ACMPR_LABB_SAMPLE)
LED_ANODE: C307.1(P) C313.1(P) C314.1(P) C315.1(P) J40.6 J40.7 J40.8 J40.9 J40.10 J41.1 J41.2 J41.3 J41.4 J41.5 J42.1 J42.2 J42.3 J42.4 J42.5 L14.1 TP168.1(P1) U35.29(ILLUM_A_FB)
LED_ANODE_B: TP171.1(P1) U35.35(ILLUM_B_FB)
LED_BLU_CATHODE: D55.C J42.6 J42.7 J42.8 J42.9 J42.10 Q19.5(D4) Q19.6(D3) Q19.7(D2) Q19.8(D1)
LED_GRN_CATHODE: D54.C J41.6 J41.7 J41.8 J41.9 J41.10 Q18.5(D4) Q18.6(D3) Q18.7(D2) Q18.8(D1)
LED_RED_CATHODE: D53.C J40.1 J40.2 J40.3 J40.4 J40.5 Q17.5(D4) Q17.6(D3) Q17.7(D2) Q17.8(D1)
LED_SEL0: R140.2 U39.B15(LED_SEL_0)
LED_SEL1: R141.2 U39.B14(LED_SEL_1)
LED_SEL_0: R140.1 R143.2 TP101.1(TP) U35.60(CH_SEL_0)
LED_SEL_1: R141.1 R142.2 TP102.1(TP) U35.61(CH_SEL_1)
LLUM_LS_DRV_Q: C321.1(P) D59.A(ANODE) Q16.4(G) R572.1(N1)
LS2_PWR: R145.1 R583.1 TP210.1(P1)
LS_PWR: R489.1 R579.1 TP209.1(P1)
NORM_PARK_GPIO8: R125.2 R788.2 U39.G14(GPIO_8) U63.4(Y)
P3P3V: R131.1 R132.1 R609.2(N2) R711.1 R789.2 U63.5(PWR) ; also on sheet 1 2 6 7 8 9 10
P3P3V_INTF: C406.1 R650.2(N2) R700.2 R717.2 TP211.1(P1) U68.5(PWR) ; also on sheet 1
PAD_RESETZ: U35.57(RESET_Z) ; also on sheet 10
PARKZ: R617.2 U35.58(INTZ) ; also on sheet 10
PATTERN_RDY: ED44.C(CATHODE) J48.3 R708.1 U56.4(Y)
PROJ_ON: R125.1 R789.1 U35.56(PROJ_ON) U63.2(A) ; also on sheet 8
PWM_IN_CAP: C326.1(P) R591.2(N2) R592.1(N1) R611.1(N1)
PWR1_B: C334.1(P) U35.97(PWR1_BOOST)
PWR1_OUT: C340.1(P) C341.1(P) L16.2 R596.1(N1) U35.94(PWR1_FB)
PWR1_SW: C334.2(N) C342.2(N) L16.1 U35.95(PWR1_SWITCH)
PWR2_B: C346.1(P) U35.76(PWR2_BOOST)
PWR2_OUT: C353.1(P) C354.1(P) L18.2 R600.1(N1) U35.72(PWR2_FB)
PWR2_SW: C346.2(N) C352.2(N) L18.1 U35.74(PWR2_SWITCH)
PWR3_OUT: C360.1(P) R604.1(N1) U35.87(PWR3_OUT)
PWR4_OUT: C367.1(P) R609.1(N1) R650.1(N1) U35.89(PWR4_OUT)
PWR_5P5V: C333.1(P) TP185.1(P1) U35.84(PWR_5P5V)
PWR_SEL: C395.1 ED30.C(CATHODE) J7.2 R693.2 R704.2 R706.2 R708.2 R712.2 R714.2 R716.2 R718.2 R720.2 R722.2 R724.2 U53.5(PWR)
PWR_TP_SEN: ED24.C(CATHODE) J36.8 J48.8 R714.1
S_CMP_OUT: R139.1 U40.A12(CMP_OUT)
S_GPIO_0: R73.1 U40.C14(GPIO_0)
S_GPIO_1: R35.1 R74.1 U40.C15(GPIO_1)
S_GPIO_2: R36.1 R75.1 U40.D14(GPIO_2)
S_GPIO_3: R37.1 R76.1 U40.D15(GPIO_3)
S_GPIO_4: R136.1 U40.E14(GPIO_4)
S_HBT_ICLK: R51.2 U40.L14(GPIO_16)
S_HBT_IDAT: R52.2 U40.L15(GPIO_17)
S_HBT_OCLK: R72.1 U40.M14(GPIO_18)
S_HBT_ODAT: R164.1 U40.M15(GPIO_19)
S_SPI1_CLK: R74.2 TP66.1(TP)
S_SPI1_CSZ0: R76.2 TP68.1(TP)
S_SPI1_DIN: R73.2 TP65.1(TP)
S_SPI1_DOUT: R75.2 TP67.1(TP)
SENS2: C310.1 R571.2(N2) TP170.1(P1) U35.78(ACMPR_IN_2)
SENS3: C318.2 R579.2 TP172.1(P1) U35.79(ACMPR_IN_3)
SENS_FOCUS: TP180.1(P1) U35.77(ACMPR_IN_1)
SENS_LABB: C325.2 R583.2 TP174.1(P1) U35.80(ACMPR_IN_LABB)
SEQ_SYNC: R126.1 TP266.1(P1) U39.K14(GPIO_14) U40.K14(GPIO_14)
SPI1_CLK: R121.2 TP95.1(TP) U35.46(SPI_CLK)
SPI1_CSZ0: R123.2 TP97.1(TP) U35.48(SPI_CS_Z)
SPI1_DIN: R120.2 R584.1(N1) TP94.1(TP)
SPI1_DOUT: R122.2 TP96.1(TP) U35.49(SPI_MOSI)
SPI_MISO: R584.2(N2) U35.47(SPI_MISO)
THERM_PWR: R574.2(N2) TP98.1(TP) U39.H15(GPIO_11)
THERMISTOR_P: ED20.C(CATHODE) J45.1 R571.1(N1) R574.1(N1) R576.1 TP169.1(P1)
TRIGGER_IN: ED25.C(CATHODE) J48.5 R812.2 U53.2(A)
TRIGGER_OUT1: ED26.C(CATHODE) J48.7 R693.1 U52.4(Y)
TRIGGER_OUT2: ED45.C(CATHODE) J48.4 R704.1 U54.4(Y)
TSTPT0: R806.2 U57.2(A) ; also on sheet 10
TSTPT1: R810.2 U61.2(A) ; also on sheet 10
TSTPT2: R807.2 U58.2(A) U68.2(A) ; also on sheet 2 10
TSTPT2_P33: J9.3 R717.1 U68.4(Y)
TSTPT3: R808.2 U59.2(A) ; also on sheet 10
TSTPT4: R813.2 U52.2(A) ; also on sheet 10
TSTPT5: R814.2 U55.2(A) ; also on sheet 10
TSTPT6: R809.2 U60.2(A) ; also on sheet 10
TSTPT7: R811.2 U66.2(A) ; also on sheet 10
VBIAS: C317.1(P) TP167.1(P1) U35.99(DMD_VBIAS) ; also on sheet 5
VOFS: C319.1(P) TP173.1(P1) U35.98(DMD_VOFFSET) ; also on sheet 5
VRST: C312.1(P) D51.A(P2) TP165.1(P1) U35.100(DMD_VRESET) ; also on sheet 5
VRST_REF: TP166.1(P1) U35.1(DRST_VRST_REF)
N21777147: R145.2 U39.J14(GPIO_12)
N21777261: R117.2 R118.2 R119.2 R131.2 R208.1
N30691593: C342.1(P) R598.1(N1)
N30691665: C352.1(P) R602.1(N1)
N38575556: C309.2(N) R578.2(N2)
N41863342: TP80.1(TP) U40.H14(GPIO_10)
N41863344: TP81.1(TP) U40.H15(GPIO_11)
N41863346: TP82.1(TP) U40.J14(GPIO_12)
N41863348: TP83.1(TP) U40.J15(GPIO_13)
N41868707: TP75.1(TP) U40.E15(GPIO_5)
N41868711: TP77.1(TP) U40.F15(GPIO_7)
N41868713: TP78.1(TP) U40.G14(GPIO_8)
N41879171: R35.2 R36.2 R37.2 R132.2 R211.1
N48401476: ED28.C(CATHODE) J7.1 R713.2
N48420581: ED29.C(CATHODE) J7.3 R711.2

Not connected (* = marked no-connect by the designer): U35 9(CH1_SWITCH_1)* 10(CH1_SWITCH_2)* 11(RLIM1_1)* 16(RLIM1_2)* 17(CH2_SWITCH_1)* 18(CH2_SWITCH_2)* 22(RLIM2_1)* 23(RLIM2_2)* 24(CH3_SWITCH_1)* 25(CH3_SWITCH_2)* 50(PWR7_BOOST)* 51(PWR7_FB)* 52(PWR7_VIN)* 53(PWR7_SWITCH)* 63(PWR6_SWITCH)* 64(PWR6_VIN)* 65(PWR6_BOOST)* 66(PWR6_FB)* 67(PWR5_VIN)* 68(PWR5_SWITCH)* 69(PWR5_BOOST)* 71(PWR5_FB)*; U40 A15(CMP_PWM)* B14(LED_SEL_1)* B15(LED_SEL_0)*

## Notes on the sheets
sheet 11
- SLAVE
- MASTER
- SLAVE
- (MASTER ID)
- (SLAVE ID)
- (GPIO_8-PROJ_ON)
- (GPIO_9)
- MASTER
- (GPIO_11)
- (GPIO_12)
- Trigger Interface
- Master Sensing Selection
- Slave Sensing Selection
- DLP018
sheet 12
- TRP DMD:
- VOFS = 10V
- VBIAS = 18V
- MAX 16A OUTPUT
- VRST = -14V
- Red LED Connector
- Green LED Connector
- Blue LED Connector
- Connect the RLIM_K pins to SENSE
  Resistor(R595) with their own  traces.
  Also connect the  RLIM_BOT_K pins
  to the bottom of  the SENSE Resistor
  with their own traces.
- (DLPC3439_GPIO_11)
- Thermistor
  CONN
- DLPC3439 1.1V  Core
- (DLPC3439_GPIO_9)
- DLPC3439 1.8V & DMD VDD
- (DLPC3439_GPIO_12)
- DLPC3439 VINTF
- DLP018
